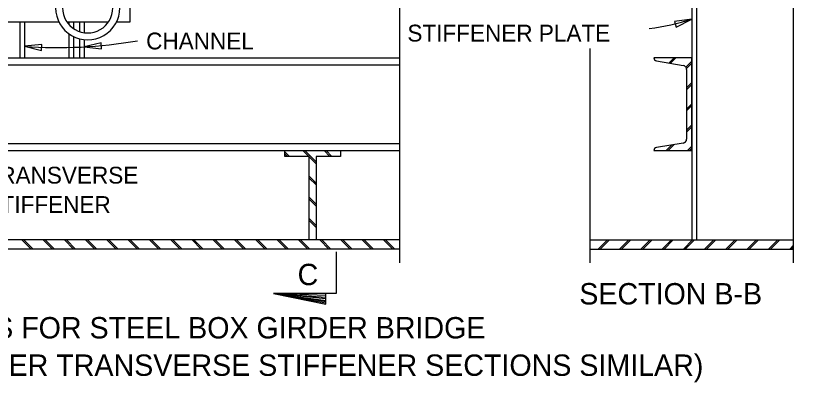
# Model space of a CAD drawing. Extents: x -1660015.2 to -1659984.9, y 2580594.2 to 2580616.7.
# Drawn here: x -1660010.01 to -1660002.95, y 2580595.52 to 2580598.81 of the extents above; entities that cross this region are included whole.
import ezdxf

# ---------------------------------------------------------------- set-up
doc = ezdxf.new("R2010")
doc.units = 0
for name, color, linetype in [('Default', 7, 'Continuous'), ('Miscellaneous', 7, 'Continuous'), ('PlotBorder_dp', 7, 'Continuous'), ('SheetLines_dp', 7, 'Continuous'), ('SteelGirder', 7, 'Continuous')]:
    doc.layers.add(name, color=color, linetype=linetype)

msp = doc.modelspace()

# ---------------------------------------------------------------- linework, layer by layer
at = {"layer": 'Default'}
for p, q in [((-1660009.9693, 2580598.7577), (-1660009.9693, 2580598.4333)), ((-1660009.9277, 2580598.7577), (-1660009.9277, 2580598.4333)), ((-1660009.5273, 2580598.7577), (-1660009.5273, 2580598.7318)), ((-1660009.4857, 2580598.7577), (-1660009.4857, 2580598.6956)), ((-1660009.4335, 2580598.7577), (-1660009.4335, 2580598.6695)), ((-1660009.3919, 2580598.7577), (-1660009.3919, 2580598.6594)), ((-1660009.5273, 2580598.6485), (-1660009.5273, 2580598.4333)), ((-1660009.4857, 2580598.6237), (-1660009.4857, 2580598.4333)), ((-1660009.4335, 2580598.6042), (-1660009.4335, 2580598.4333)), ((-1660009.3919, 2580598.5964), (-1660009.3919, 2580598.4333))]:
    msp.add_line(p, q, dxfattribs=at)
for radius, start, end in [(0.2882, 179.99549, 0.00006), (0.2257, 180, 0.00003)]:
    msp.add_arc((-1660009.3595, 2580598.8827), radius, start, end, dxfattribs=at)
at = {"layer": 'Miscellaneous'}
for p, q in [((-1660004.2774, 2580598.4276), (-1660004.2717, 2580598.4333)), ((-1660004.1447, 2580598.387), (-1660004.0984, 2580598.4333)), ((-1660004.1295, 2580598.3845), (-1660004.0808, 2580598.4333)), ((-1660003.9922, 2580598.3487), (-1660003.9374, 2580598.4034)), ((-1660003.9867, 2580598.3364), (-1660003.9374, 2580598.3857)), ((-1660003.9853, 2580598.1646), (-1660003.9374, 2580598.2125)), ((-1660003.9853, 2580598.1469), (-1660003.9374, 2580598.1948)), ((-1660003.9853, 2580597.9737), (-1660003.9374, 2580598.0216)), ((-1660003.9853, 2580597.956), (-1660003.9374, 2580598.0039)), ((-1660003.9853, 2580597.7827), (-1660003.9374, 2580597.8307)), ((-1660003.9853, 2580597.7651), (-1660003.9374, 2580597.813)), ((-1660004.1504, 2580597.6), (-1660004.0963, 2580597.6541)), ((-1660007.5494, 2580597.5479), (-1660007.5918, 2580597.5903)), ((-1660007.3762, 2580597.5479), (-1660007.4283, 2580597.6)), ((-1660007.3105, 2580597.4999), (-1660007.4107, 2580597.6)), ((-1660007.1853, 2580597.5479), (-1660007.2374, 2580597.6)), ((-1660007.1676, 2580597.5479), (-1660007.2197, 2580597.6)), ((-1660004.1681, 2580597.6), (-1660004.1174, 2580597.6507)), ((-1660003.9772, 2580597.6), (-1660003.9374, 2580597.6397)), ((-1660003.9595, 2580597.6), (-1660003.9374, 2580597.6221)), ((-1660007.5671, 2580597.5479), (-1660007.5918, 2580597.5726)), ((-1660007.3105, 2580597.4822), (-1660007.373, 2580597.5446)), ((-1660007.3105, 2580597.309), (-1660007.373, 2580597.3714)), ((-1660007.3105, 2580597.2913), (-1660007.373, 2580597.3537)), ((-1660007.3105, 2580597.118), (-1660007.373, 2580597.1805)), ((-1660007.3105, 2580597.1004), (-1660007.373, 2580597.1628)), ((-1660007.3105, 2580596.9271), (-1660007.373, 2580596.9896)), ((-1660007.3105, 2580596.9094), (-1660007.373, 2580596.9719)), ((-1660009.8673, 2580596.7147), (-1660009.9506, 2580596.798)), ((-1660009.8496, 2580596.7147), (-1660009.9329, 2580596.798)), ((-1660009.6764, 2580596.7147), (-1660009.7597, 2580596.798)), ((-1660009.6587, 2580596.7147), (-1660009.742, 2580596.798)), ((-1660009.4855, 2580596.7147), (-1660009.5687, 2580596.798)), ((-1660009.4678, 2580596.7147), (-1660009.5511, 2580596.798)), ((-1660009.2945, 2580596.7147), (-1660009.3778, 2580596.798)), ((-1660009.2769, 2580596.7147), (-1660009.3602, 2580596.798)), ((-1660009.1036, 2580596.7147), (-1660009.1869, 2580596.798)), ((-1660009.086, 2580596.7147), (-1660009.1692, 2580596.798)), ((-1660008.9127, 2580596.7147), (-1660008.996, 2580596.798)), ((-1660008.895, 2580596.7147), (-1660008.9783, 2580596.798)), ((-1660008.7218, 2580596.7147), (-1660008.8051, 2580596.798)), ((-1660008.7041, 2580596.7147), (-1660008.7874, 2580596.798)), ((-1660008.5309, 2580596.7147), (-1660008.6142, 2580596.798)), ((-1660008.5132, 2580596.7147), (-1660008.5965, 2580596.798)), ((-1660008.34, 2580596.7147), (-1660008.4232, 2580596.798)), ((-1660008.3223, 2580596.7147), (-1660008.4056, 2580596.798)), ((-1660008.149, 2580596.7147), (-1660008.2323, 2580596.798)), ((-1660008.1314, 2580596.7147), (-1660008.2146, 2580596.798)), ((-1660007.9581, 2580596.7147), (-1660008.0414, 2580596.798)), ((-1660007.9404, 2580596.7147), (-1660008.0237, 2580596.798)), ((-1660007.7672, 2580596.7147), (-1660007.8505, 2580596.798)), ((-1660007.7495, 2580596.7147), (-1660007.8328, 2580596.798)), ((-1660007.5763, 2580596.7147), (-1660007.6596, 2580596.798)), ((-1660007.5586, 2580596.7147), (-1660007.6419, 2580596.798)), ((-1660007.3854, 2580596.7147), (-1660007.4686, 2580596.798)), ((-1660007.3677, 2580596.7147), (-1660007.451, 2580596.798)), ((-1660007.3722, 2580596.7979), (-1660007.373, 2580596.7986)), ((-1660007.1944, 2580596.7147), (-1660007.2777, 2580596.798)), ((-1660007.1768, 2580596.7147), (-1660007.26, 2580596.798)), ((-1660007.0035, 2580596.7147), (-1660007.0868, 2580596.798)), ((-1660006.9858, 2580596.7147), (-1660007.0691, 2580596.798)), ((-1660006.8126, 2580596.7147), (-1660006.8959, 2580596.798)), ((-1660006.7949, 2580596.7147), (-1660006.8782, 2580596.798)), ((-1660006.6217, 2580596.7147), (-1660006.705, 2580596.798)), ((-1660006.604, 2580596.7147), (-1660006.6873, 2580596.798)), ((-1660004.7785, 2580596.7147), (-1660004.6952, 2580596.798)), ((-1660004.7608, 2580596.7147), (-1660004.6775, 2580596.798)), ((-1660004.5876, 2580596.7147), (-1660004.5043, 2580596.798)), ((-1660004.5699, 2580596.7147), (-1660004.4866, 2580596.798)), ((-1660004.3967, 2580596.7147), (-1660004.3134, 2580596.798)), ((-1660004.379, 2580596.7147), (-1660004.2957, 2580596.798)), ((-1660004.2057, 2580596.7147), (-1660004.1225, 2580596.798)), ((-1660004.1881, 2580596.7147), (-1660004.1048, 2580596.798)), ((-1660004.0148, 2580596.7147), (-1660003.9315, 2580596.798)), ((-1660003.9971, 2580596.7147), (-1660003.9139, 2580596.798)), ((-1660003.8239, 2580596.7147), (-1660003.7406, 2580596.798)), ((-1660003.8062, 2580596.7147), (-1660003.7229, 2580596.798)), ((-1660003.633, 2580596.7147), (-1660003.5497, 2580596.798)), ((-1660003.6153, 2580596.7147), (-1660003.532, 2580596.798)), ((-1660003.4421, 2580596.7147), (-1660003.3588, 2580596.798)), ((-1660003.4244, 2580596.7147), (-1660003.3411, 2580596.798)), ((-1660003.2511, 2580596.7147), (-1660003.1679, 2580596.798)), ((-1660003.2335, 2580596.7147), (-1660003.1502, 2580596.798)), ((-1660003.0602, 2580596.7147), (-1660003.0252, 2580596.7497)), ((-1660003.0426, 2580596.7147), (-1660003.0252, 2580596.732))]:
    msp.add_line(p, q, dxfattribs=at)
at = {"layer": 'SheetLines_dp'}
for p, q in [((-1660007.224, 2580596.2976), (-1660007.6928, 2580596.3151)), ((-1660007.6928, 2580596.3151), (-1660007.224, 2580596.2826)), ((-1660007.224, 2580596.2688), (-1660007.6928, 2580596.3151)), ((-1660007.6928, 2580596.3151), (-1660007.224, 2580596.2551)), ((-1660007.224, 2580596.2426), (-1660007.6928, 2580596.3151)), ((-1660007.6928, 2580596.3151), (-1660007.224, 2580596.2326))]:
    msp.add_line(p, q, dxfattribs=at)
for points in [[(-1660003.0252, 2580596.5919), (-1660003.0252, 2580600.3516), (-1660003.1027, 2580600.3516), (-1660003.0252, 2580600.3853), (-1660002.9477, 2580600.4191), (-1660003.0252, 2580600.4191), (-1660003.0252, 2580604.252)], [(-1660006.558, 2580596.5919), (-1660006.558, 2580600.3516), (-1660006.6355, 2580600.3516), (-1660006.558, 2580600.3853), (-1660006.4805, 2580600.4191), (-1660006.558, 2580600.4191), (-1660006.558, 2580601.7115)], [(-1660004.8501, 2580596.5919), (-1660004.8501, 2580598.5185)], [(-1660007.1303, 2580596.6901), (-1660007.1302, 2580596.3151), (-1660007.6928, 2580596.3151), (-1660007.224, 2580596.2213), (-1660007.224, 2580596.3151)]]:
    msp.add_lwpolyline(points, dxfattribs=at)
for points in [[(-1660003.9375, 2580598.7819), (-1660004.0944, 2580598.7601), (-1660004.0784, 2580598.7097)], [(-1660009.9277, 2580598.5378), (-1660009.774, 2580598.4994), (-1660009.77, 2580598.5522)], [(-1660009.3919, 2580598.5321), (-1660009.2345, 2580598.5144), (-1660009.2375, 2580598.5673)]]:
    msp.add_lwpolyline(points, close=True, dxfattribs=at)
for centre, radius, start, end in [((-1660004.6283, 2580600.9723), 2.2968, 277.70147, 287.50633), ((-1660009.6175, 2580602.5711), 4.0453, 265.60117, 280.01859)]:
    msp.add_arc(centre, radius, start, end, dxfattribs=at)
at = {"layer": 'SteelGirder'}
for p, q in [((-1660003.9374, 2580603.0403), (-1660003.9374, 2580596.798)), ((-1660003.8957, 2580603.0403), (-1660003.8957, 2580596.798)), ((-1660011.3671, 2580598.4332), (-1660006.558, 2580598.4332)), ((-1660003.9374, 2580598.4333), (-1660004.2791, 2580598.4333)), ((-1660003.9374, 2580597.6), (-1660003.9374, 2580598.4333)), ((-1660011.3671, 2580598.3708), (-1660006.558, 2580598.3708)), ((-1660004.2552, 2580598.4051), (-1660004.0166, 2580598.3661)), ((-1660003.9853, 2580598.3291), (-1660003.9853, 2580597.7041)), ((-1660011.3671, 2580597.6625), (-1660006.558, 2580597.6625)), ((-1660004.0166, 2580597.6671), (-1660004.2552, 2580597.6282)), ((-1660011.3671, 2580597.6), (-1660006.558, 2580597.6)), ((-1660004.2791, 2580597.6), (-1660003.9374, 2580597.6)), ((-1660007.3416, 2580596.798), (-1660010.8417, 2580596.798)), ((-1660006.558, 2580596.798), (-1660007.3416, 2580596.798)), ((-1660004.8501, 2580596.798), (-1660003.0252, 2580596.798)), ((-1660006.558, 2580596.7147), (-1660011.5725, 2580596.7147)), ((-1660004.8501, 2580596.7147), (-1660003.0252, 2580596.7147))]:
    msp.add_line(p, q, dxfattribs=at)
for points in [[(-1660009.0999, 2580598.7577), (-1660008.9775, 2580598.7577), (-1660008.9775, 2580602.0077), (-1660009.8656, 2580602.0077)], [(-1660010.4775, 2580600.8659), (-1660010.4775, 2580598.7577), (-1660009.6191, 2580598.7577)], [(-1660009.5474, 2580598.7577), (-1660009.1716, 2580598.7577)]]:
    msp.add_lwpolyline(points, dxfattribs=at)
msp.add_lwpolyline([(-1660007.373, 2580596.7979), (-1660007.373, 2580597.5479), (-1660007.5918, 2580597.5479), (-1660007.5918, 2580597.6), (-1660007.0918, 2580597.6), (-1660007.0918, 2580597.5479), (-1660007.3105, 2580597.5479), (-1660007.3105, 2580596.7979)], close=True, dxfattribs=at)
for centre, radius, start, end in [((-1660004.2505, 2580598.4333), 0.0286, 180, 260.5), ((-1660004.0228, 2580598.3291), 0.0375, 360, 80.5), ((-1660004.0228, 2580597.7041), 0.0375, 279.5, 360), ((-1660004.2505, 2580597.6), 0.0286, 99.5, 180)]:
    msp.add_arc(centre, radius, start, end, dxfattribs=at)

# ---------------------------------------------------------------- texts
at = {"layer": 'PlotBorder_dp'}
for s, height, p in [('CHANNEL', 0.1512, (-1660008.8351, 2580598.5091)), ('C', 0.192, (-1660007.476, 2580596.3914)), ('SECTION B-B', 0.192, (-1660004.9484, 2580596.2181))]:
    msp.add_text(s, height=height, dxfattribs=at).set_placement(p)
at = {"layer": 'SheetLines_dp'}
for s, height, p in [('STIFFENER PLATE', 0.1512, (-1660006.4909, 2580598.5799)), ('TRANSVERSE', 0.1512, (-1660010.2761, 2580597.3039)), ('STIFFENER', 0.1512, (-1660010.2761, 2580597.0398)), ('LIGHTING DETAILS FOR STEEL BOX GIRDER BRIDGE', 0.192, (-1660012.3816, 2580595.9128)), ('(CROSS FRAME SECTION SHOWN, OTHER TRANSVERSE STIFFENER SECTIONS SIMILAR)', 0.192, (-1660014.9904, 2580595.5768))]:
    msp.add_text(s, height=height, dxfattribs=at).set_placement(p)

doc.saveas('drawing.dxf')
